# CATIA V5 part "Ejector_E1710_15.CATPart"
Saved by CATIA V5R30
Part number: Vyhazovac_4x160_3
Nomenclature: E1710/4x160
Description: MEUSBURGER
Property "Material": "1.221"
Publications: "__DrillHole", "Base"
Bounding box of the stored display mesh (mm): x -3.996 to 3.996, y -3.999 to 3.999, z 0 to 152
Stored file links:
  E:\Bakalarka\Model\Forma_v7\Ejector_E1710_15.CATPart
  E:\dev\MoldDesign\intel_a\startup\components\MoldCatalog\Ejector\Meusburger\Ejector_E1710\TableE1710.txt
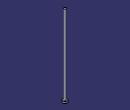
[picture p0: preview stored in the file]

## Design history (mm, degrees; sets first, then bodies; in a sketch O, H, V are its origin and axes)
Parameters
  Ref = "E1710/4x160" {design table}
  D1 = 4 mm {design table}
  D3 = 8 mm {design table}
  L = 160 mm {design table}
  L3 = 3 mm {design table}
  R = 0.3 mm {design table}
  k_d3 = 9 mm {design table}
  k_d1 = 4.2 mm {design table}
  k_F = 0.3 mm {design table}
  kl = 17 mm {design table}
  Mat = "1.221" {design table}
  HeatTreat = "ISO6751" {design table}
  Offset_Parting = 10 mm
  Anti_Rotation = "Normal"
  Anti_Rotation_D = 2.3 mm
  Anti_Rotation_D_Icut = 2.3 mm
  Add_Length_L = 0.8377 mm
  Add_Length_D3 = 0 mm
  SupplierRef = "Meusburger 2017"
  BmpRef = "F_MldEjectorD1"
  DrillHole_Length = 225 mm
  ValidationTest = false
  Anti_Rotation_D_min = 2.3 mm {= OffSet_D1 /2}
  Anti_Rotation_D_max = 3.925 mm {= D3/2-0.075mm}
  Anti_Rotation_D_ref = 2.3 mm {= Anti_Rotation_D}
  Anti_Rotation_D_Icut_ref = 2.3 mm {= Anti_Rotation_D_Icut}
  Anti_Rotation_Ref_Icut = 2.3246 mm
  Offset_L = 20 mm
  D = 4 mm {= D1}
  OffSet_D1 = 4.6 mm {= D1+2*R}
  OffSet_D3 = 9 mm {= D3+1mm}
  XG_Split = -24 mm
  YG_Split = 21.5 mm
  ZG_Split = -198 mm
  DirX_Split = 0 mm
  DirY_Split = 0 mm
  DirZ_Split = 1 mm
Set1 "BaseBody"
  Point1 "Base": (0, 0, 0)
  Plane1: type Offset, RefPlane xy-plane, Offset 225 {= DrillHole_Length}, reversed
  Sketch1 "Sketch.2" on xy-plane, origin (0, 0, 0), H (1, 0, 0), V (0, 1, 0)
    point P1 (-0.46, 1.1623)
    point P2 (0.46, 1.1623)
    construction line L1 (-0.46, 1.1623) -> (0.46, 1.1623)
    point P3 (0.46, -1.1623)
    line L2 (0.46, -1.1623) -> (0.46, 1.1623)
    point P4 (-0.46, -1.1623)
    construction line L3 (0.46, -1.1623) -> (-0.46, -1.1623)
    line L4 (-0.46, 1.1623) -> (-0.46, -1.1623)
    point P5 (-0.21, 1.1623)
    arc A1 centre (-0.21, 1.1623) radius 0.25 from (-0.21, 1.4123) to (-0.46, 1.1623) ccw
    point P7 (0.21, 1.1623)
    point P8 (0.21, 1.4123)
    arc A2 centre (0.21, 1.1623) radius 0.25 from (0.46, 1.1623) to (0.21, 1.4123) ccw
    line L5 (-0.21, 1.4123) -> (0.21, 1.4123)
    point P9 (-0.46, -1.1623)
    arc A3 centre (-0.21, -1.1623) radius 0.25 from (-0.46, -1.1623) to (-0.21, -1.4123) ccw
    point P11 (0.21, -1.4123)
    line L6 (-0.21, -1.4123) -> (0.21, -1.4123)
    point P12 (0.46, -1.1623)
    arc A4 centre (0.21, -1.1623) radius 0.25 from (0.21, -1.4123) to (0.46, -1.1623) ccw
    point P14 (-0.46, 1.1623)
    point P15 (-0.46, -1.1623)
    point P16 (0.46, 1.1623)
    point P17 (0.46, -1.1623)
    reference projected circle E1 centre (0, 0) radius 1.25 from edge [face of Shaft1 from Sketch2.L3 | face of Shaft1 from Sketch2.L4]
    reference projected circle E2 centre (0, 0) radius 1.25 from edge [face of Shaft1 from Sketch2.L3 | face of Shaft1 from Sketch2.L4]
    reference projected circle E3 centre (0, 0) radius 1.25 from edge [face of Shaft1 from Sketch2.L3 | face of Shaft1 from Sketch2.L4]
    reference projected circle E4 centre (0, 0) radius 1.25 from edge [face of Shaft1 from Sketch2.L3 | face of Shaft1 from Sketch2.L4]
    point P18 (-0.46, -1.1623)
    point P19 (-0.21, -1.4123)
    point P20 (0.21, -1.4123)
    point P21 (0.46, -1.1623)
    point P22 (-0.21, -1.4123)
    point P23 (0.21, -1.4123)
    distance P14 P15 = 2.3246 (reference)
    distance P16 P17 = 2.3246 (reference)
    distance L1 P14 = 0 (reference)
    radius A1 = 2
    distance L4 V = 2.31
    distance L2 V = 3.935
    distance L5 L6 = 8
    horizontal: L1 H, L3 H, L5 H
    vertical: L2 V, L4 V
    coincidence: P5 L1, P7 L1, P3 P12, P14 L4, P15 L4, P16 L2, P17 L2, P14 E1, P15 E2, P16 E3, P17 E4, P3 P21, P4 P18, P20 P23, P19 P22
    tangency: A1 L4, A2 L2, A2 L5, A1 L5
    symmetry: P1 P9 H, A1 A3 H, P8 P11 H, L5 L6 H, P2 P12 H, A2 A4 H
  DatumSurface1
Body1 "PartBody" (main body)
  Sketch2 "Sketch.1" on zx-plane, origin (0, 0, 0), H (-1, 0, 0), V (0, 0, 1)
    point P1 (0, 160)
    line L1 (2, 160) -> (0, 160)
    line L2 (2, 3) -> (2, 160)
    line L3 (4, 3) -> (2, 3)
    line L4 (4, 0) -> (4, 3)
    point P5 (0, 0)
    line L5 (0, 0) -> (4, 0)
    point P6 (0, 160)
    axis line L6 (0, 160) -> (0, 0)
    point P7 (0, 0)
    point P8 (2, 3)
    point P9 (2, 3)
    line L7 (0, 160) -> (0, 0)
    distance L5 L3 = 3 {= L3}
    distance L5 L1 = 160 {= L}
    distance L2 L6 = 2 {= D1 /2}
    distance L4 L6 = 4 {= D3 /2}
    coincidence: L6 P5, P1 L6, L5 H, L6 V, P7 O, P6 P1, P8 P9
    vertical: L2 V, L7 V
    horizontal: L1 H
  Shaft1 "Shaft.1": profile Sketch2, axis Sketch2.L6, angle 360
  Pocket1: profile face of Shaft1 from Sketch2.L1, direction along face of Shaft1 from Sketch2.L1 reversed, up to face of DatumSurface1
  Pocket2 "Pocket.1": profile Sketch1, direction (0, 0, 1), length 4, outer side, deactivated
  Pocket3 "Pocket.2": profile Sketch1, direction (0, 0, 1), length 4, outer side, deactivated
  Fillet1: radius 0.3 {= R}, on edge [face of Shaft1 from Sketch2.L2 | face of Shaft1 from Sketch2.L3]
Body2 "__DrillHole"
  Sketch3 "Sketch.3" on face of Shaft1, origin (0, 0, 0), H (1, 0, 0), V (0, -1, 0)
    point P1 (0, 0)
    reference projected point E1 (0, 0) from Point1
    coincidence: E1 P1
  Hole1 "Hole.1": placed by Sketch3, at (0, 0, 0) direction (0, 0, 1), diameter 4.6 {= OffSet_D1}, depth 140 {= L-Offset_L}
  Sketch4 "Sketch.4" on face of Shaft1, origin (0, 0, 0), H (1, 0, 0), V (0, -1, 0)
    point P1 (0, 0)
    reference projected point E1 (0, 0) from Point1
    coincidence: E1 P1
  Hole2 "Hole.2": placed by Sketch4, at (0, 0, 0) direction (0, 0, 1), diameter 4 {= D1}, depth 160 {= L}
  Sketch5 "Sketch.5" on face of Shaft1 from Sketch2.L3, origin (0, 0, 3), H (1, 0, 0), V (0, 1, 0)
    point P1 (0, 0)
    reference projected point E1 (0, 0) from Point1
    coincidence: E1 P1
  Hole3 "Hole.3": placed by Sketch5, at (0, 0, 3) direction (0, 0, -1), diameter 9 {= OffSet_D3}, depth 228 {= L3 +DrillHole_Length}
  Chamfer1: length 0.3 {= k_F}, angle 45, on edge [face of Hole1 | face of Hole3]
  Body3 "__Body.1"
    Pocket4 "Pocket.3": profile Sketch1, direction (0, 0, -1), length 225, opposite side length 3, deactivated
  Assemble1: tool Body3
  Chamfer2: length 0.3 {= k_F}, angle 45, on edge [start face of Pocket4 | face of Hole1], deactivated
  Body4 "__Body.2"
    Pocket5 "Pocket.4": profile Sketch1, direction (0, 0, -1), length 225, opposite side length 3, deactivated
  Assemble2: tool Body4
  Chamfer3: length 0.3 {= k_F}, angle 45, on edge [start face of Pocket5 | face of Hole1], deactivated
Current feature: Pocket1
Relations
  design table "TableE1710", configuration 187, drives Ref, D1, D3, L, L3, R, k_d3, k_d1, k_F, kl, Mat, HeatTreat
  Offset_L = 20mm (deactivated)
  rule "Cut_Head_rule":
    let sketch_cut (length)
    let PartBody_Pocket_Sketch (Boolean)
    let I_PartBody_Pocket (Boolean)
    let D_PartBody_Pocket (Boolean)
    let N_DrillHole_Hole (Boolean)
    let N_DrillHole_Hole_Sketch (Boolean)
    let I_DrillHole_Pocket (Boolean)
    let D_DrillHole_Pocket (Boolean)
    /* --------------------------------------------------------------------------------------*/
    if Anti_Rotation =="Normal"
    {
    	sketch_cut=Anti_Rotation_D_max
    	PartBody_Pocket_Sketch = false
    	I_PartBody_Pocket = false
    	D_PartBody_Pocket = false
    	N_DrillHole_Hole = true
    	N_DrillHole_Hole_Sketch = true
    	I_DrillHole_Pocket = false
    	D_DrillHole_Pocket = false
    	Chamfer1.Activity= true
    	Chamfer2.Activity= false
    	Chamfer3.Activity= false
    }
    if Anti_Rotation == "I_Cut"
    {
    	sketch_cut=Anti_Rotation_D_Icut_ref
    	PartBody_Pocket_Sketch = true
    	I_PartBody_Pocket = true
    	D_PartBody_Pocket = false
    	N_DrillHole_Hole = false
    	N_DrillHole_Hole_Sketch = false
    	I_DrillHole_Pocket = true
    	D_DrillHole_Pocket = false
    	Chamfer1.Activity= false
    	Chamfer2.Activity= true
    	Chamfer3.Activity= false
    }
    if Anti_Rotation =="D_Cut"
    {
    	sketch_cut=Anti_Rotation_D_max
    	PartBody_Pocket_Sketch = true
    	I_PartBody_Pocket = false
    	D_PartBody_Pocket = true
    	N_DrillHole_Hole = false
    	N_DrillHole_Hole_Sketch = false
    	I_DrillHole_Pocket = false
    	D_DrillHole_Pocket = true
    	Chamfer1.Activity= false
    	Chamfer2.Activity= false
    	Chamfer3.Activity= true
    }
    /* --------------------------------------------------------------------------------------*/
    Sketch1.distance(L2 V) = sketch_cut+0.01mm
    Sketch1.distance(L4 V) =Anti_Rotation_D_ref+0.01mm
    Sketch1.radius(A1) =D/2
    Pocket4.FirstLimit.Depth = DrillHole_Length
    Pocket5.FirstLimit.Depth = DrillHole_Length
    Pocket2.FirstLimit.Depth = L3+1mm
    Pocket3.FirstLimit.Depth = L3+1mm
    Pocket4.SecondLimit.Depth = L3
    Pocket5.SecondLimit.Depth =L3
    Pocket2.Activity = I_PartBody_Pocket
    Pocket3.Activity = D_PartBody_Pocket
    Sketch1.Activity =PartBody_Pocket_Sketch
    Hole3.Activity= N_DrillHole_Hole
    Sketch5.Activity = N_DrillHole_Hole_Sketch
    Pocket4.Activity = I_DrillHole_Pocket
    Pocket5.Activity  = D_DrillHole_Pocket
  rule "Anti_Rotation_Icut_constrain":
    let Ref1(length)
    let Ref2(length)
    let Ref3(length)
    let Diam1(length)
    let Diam2(length)
    let Add_Length_Lmin (length)
    Ref1=Sketch1.distance(P14 P15)
    Ref2=Sketch1.distance(P16 P17)
    Diam1=D
    Diam2=D3
    /* --------------------------------------------------------------------*/
    if Ref1 >Ref2
    	Anti_Rotation_Ref_Icut = Ref1
    else
    	Anti_Rotation_Ref_Icut  =Ref2
    Add_Length_D3 .InferiorRange=Anti_Rotation_Ref_Icut /2+Diam1/2 -Diam2/2
    if Add_Length_D3 .InferiorRange<0mm
    	Add_Length_D3 .InferiorRange=0mm
    if ValidationTest == "true"
    	Ref3   = 2*Add_Length_L +Anti_Rotation_Ref_Icut  +2*Diam1/2
    else
    	Ref3  =Diam2+2*Add_Length_D3
    if Ref3 <Diam2
    {
    	Ref3 =Diam2
    }
    /* --------------------------------------------------------------------*/
    Sketch1.distance(L5 L6) = Ref3
    Add_Length_L .InferiorRange=Diam2/2-Anti_Rotation_Ref_Icut/2-Diam1/2
    Add_Length_Lmin=Diam2/2-Anti_Rotation_Ref_Icut/2-Diam1/2
    if Add_Length_Lmin<0mm
    	Add_Length_L .InferiorRange=0mm
    else
    	Add_Length_L .InferiorRange=Add_Length_Lmin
